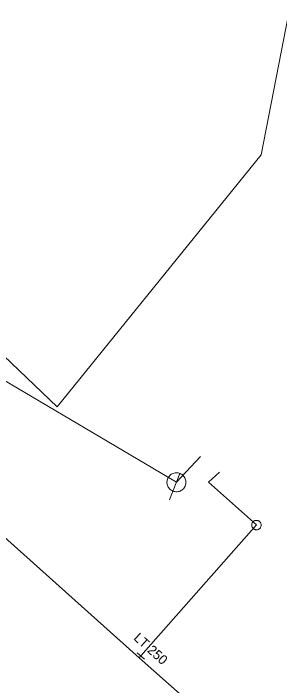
# Model space of a CAD drawing. Extents: x -807203 to -805207, y -993656 to -992505.
# Drawn here: x -805939.1 to -805911, y -993352 to -993281.2 of the extents above; entities that cross this region are included whole.
import ezdxf

# ---------------------------------------------------------------- set-up
doc = ezdxf.new("R2010")
doc.units = 0
doc.header["$LTSCALE"] = 0.4
for name, color, linetype, lineweight in [('1', 7, 'Continuous', 13), ('11', 7, 'Continuous', 13), ('13', 7, 'Continuous', 13), ('14', 7, 'Continuous', 25), ('17', 7, 'Continuous', 25), ('22', 7, 'Continuous', 13), ('23', 7, 'Continuous', 13), ('34', 7, 'Continuous', 13)]:
    doc.layers.add(name, color=color, linetype=linetype, lineweight=lineweight)

msp = doc.modelspace()

# ---------------------------------------------------------------- linework, layer by layer
at = {"layer": '11'}
msp.add_lwpolyline([(-805919.353, -993327.844), (-805921.873, -993330.572), (-805943.489, -993317.82)], dxfattribs=at)
at = {"layer": '13'}
msp.add_line((-805925.634, -993348.875), (-805913.442, -993335.051), dxfattribs=at)
for points in [[(-805946.515, -993311.099), (-805934.429, -993322.629), (-805912.935, -993296.079), (-805909.259, -993277.126), (-805870.365, -993236.01)], [(-805913.442, -993335.051), (-805918.497, -993330.563), (-805917.348, -993329.5)]]:
    msp.add_lwpolyline(points, dxfattribs=at)
at = {"layer": '14', "lineweight": 13}
msp.add_line((-805925.796, -993349.072), (-805925.634, -993348.875), dxfattribs=at)
at = {"layer": '17'}
msp.add_lwpolyline([(-805980.27, -993297.811), (-805964.539, -993313.096), (-805944.059, -993332.754), (-805925.796, -993349.072), (-805905.688, -993366.883), (-805894.556, -993375.978), (-805881.298, -993386.71), (-805877.651, -993389.561), (-805871.269, -993394.798), (-805850.666, -993411.467), (-805839.3, -993421.037), (-805830.275, -993428.564)], dxfattribs=at)
at = {"layer": '22'}
msp.add_line((-805922.615, -993332.429), (-805921.501, -993329.643), dxfattribs=at)
msp.add_lwpolyline([(-805920.944, -993330.943), (-805920.909, -993330.84), (-805920.886, -993330.733), (-805920.874, -993330.623), (-805920.874, -993330.515), (-805920.886, -993330.405), (-805920.91, -993330.299), (-805920.947, -993330.195), (-805920.993, -993330.096), (-805921.051, -993330.002), (-805921.117, -993329.916), (-805921.194, -993329.838), (-805921.279, -993329.768), (-805921.37, -993329.708), (-805921.467, -993329.658), (-805921.57, -993329.619), (-805921.676, -993329.592), (-805921.784, -993329.576), (-805921.894, -993329.572), (-805922.003, -993329.581), (-805922.11, -993329.6), (-805922.215, -993329.633), (-805922.316, -993329.676), (-805922.412, -993329.73), (-805922.5, -993329.793), (-805922.581, -993329.866), (-805922.654, -993329.948), (-805922.718, -993330.038), (-805922.771, -993330.133), (-805922.814, -993330.235), (-805922.845, -993330.339), (-805922.865, -993330.447), (-805922.872, -993330.556), (-805922.868, -993330.665), (-805922.853, -993330.774), (-805922.824, -993330.88), (-805922.785, -993330.982), (-805922.735, -993331.079), (-805922.674, -993331.17), (-805922.604, -993331.254), (-805922.525, -993331.33), (-805922.438, -993331.397), (-805922.345, -993331.454), (-805922.245, -993331.5), (-805922.141, -993331.535), (-805922.034, -993331.558), (-805921.926, -993331.57), (-805921.816, -993331.57), (-805921.707, -993331.558), (-805921.6, -993331.534), (-805921.497, -993331.499), (-805921.398, -993331.452), (-805921.304, -993331.395), (-805921.218, -993331.328), (-805921.14, -993331.252), (-805921.069, -993331.168), (-805921.009, -993331.076), (-805920.959, -993330.978)], close=True, dxfattribs=at)
at = {"layer": '23'}
for points in [[(-805913.113, -993334.704), (-805913.155, -993334.672), (-805913.2, -993334.644), (-805913.246, -993334.623), (-805913.296, -993334.605), (-805913.346, -993334.592), (-805913.399, -993334.586), (-805913.451, -993334.584), (-805913.502, -993334.588), (-805913.554, -993334.597), (-805913.604, -993334.611), (-805913.653, -993334.631), (-805913.7, -993334.656), (-805913.743, -993334.685), (-805913.782, -993334.719), (-805913.818, -993334.756), (-805913.851, -993334.799), (-805913.878, -993334.842), (-805913.901, -993334.891), (-805913.919, -993334.938), (-805913.932, -993334.989), (-805913.938, -993335.042), (-805913.939, -993335.094), (-805913.935, -993335.147), (-805913.927, -993335.198), (-805913.912, -993335.248), (-805913.891, -993335.297), (-805913.867, -993335.342), (-805913.837, -993335.385), (-805913.803, -993335.425), (-805913.766, -993335.462), (-805913.725, -993335.494), (-805913.68, -993335.521), (-805913.633, -993335.545), (-805913.584, -993335.562), (-805913.534, -993335.573), (-805913.482, -993335.58), (-805913.429, -993335.583), (-805913.376, -993335.579), (-805913.325, -993335.569)], [(-805913.325, -993335.569), (-805913.276, -993335.556), (-805913.227, -993335.535), (-805913.181, -993335.511), (-805913.137, -993335.48), (-805913.098, -993335.447), (-805913.062, -993335.41), (-805913.03, -993335.368), (-805913.002, -993335.324), (-805912.979, -993335.276), (-805912.962, -993335.227), (-805912.949, -993335.176), (-805912.941, -993335.125), (-805912.941, -993335.072), (-805912.944, -993335.02), (-805912.953, -993334.969), (-805912.968, -993334.918), (-805912.988, -993334.869), (-805913.013, -993334.823), (-805913.043, -993334.781), (-805913.076, -993334.741), (-805913.113, -993334.704), (-805913.155, -993334.672), (-805913.2, -993334.644), (-805913.246, -993334.623), (-805913.296, -993334.605), (-805913.346, -993334.592), (-805913.399, -993334.586), (-805913.451, -993334.584), (-805913.502, -993334.588), (-805913.554, -993334.597), (-805913.604, -993334.611), (-805913.653, -993334.631), (-805913.7, -993334.656), (-805913.743, -993334.685), (-805913.782, -993334.719), (-805913.818, -993334.756), (-805913.851, -993334.799), (-805913.878, -993334.842), (-805913.901, -993334.891)], [(-805913.013, -993334.823), (-805913.043, -993334.781), (-805913.076, -993334.741), (-805913.113, -993334.704)], [(-805913.901, -993334.891), (-805913.919, -993334.938), (-805913.932, -993334.989), (-805913.938, -993335.042), (-805913.939, -993335.094), (-805913.935, -993335.147), (-805913.927, -993335.198), (-805913.912, -993335.248), (-805913.891, -993335.297), (-805913.867, -993335.342), (-805913.837, -993335.385), (-805913.803, -993335.425), (-805913.766, -993335.462), (-805913.725, -993335.494), (-805913.68, -993335.521), (-805913.633, -993335.545), (-805913.584, -993335.562), (-805913.534, -993335.573), (-805913.482, -993335.58), (-805913.429, -993335.583), (-805913.376, -993335.579), (-805913.325, -993335.569), (-805913.276, -993335.556), (-805913.227, -993335.535), (-805913.181, -993335.511), (-805913.137, -993335.48), (-805913.098, -993335.447), (-805913.062, -993335.41), (-805913.03, -993335.368), (-805913.002, -993335.324), (-805912.979, -993335.276), (-805912.962, -993335.227), (-805912.949, -993335.176), (-805912.941, -993335.125), (-805912.941, -993335.072), (-805912.944, -993335.02), (-805912.953, -993334.969), (-805912.968, -993334.918), (-805912.988, -993334.869), (-805913.013, -993334.823)]]:
    msp.add_lwpolyline(points, dxfattribs=at)
at = {"layer": '34'}
msp.add_line((-805926.021, -993348.558), (-805925.247, -993349.192), dxfattribs=at)

# ---------------------------------------------------------------- texts
at = {"layer": '1'}
msp.add_text('LT 250', height=1, rotation=318, dxfattribs=at).set_placement((-805926.459, -993347.087))

doc.saveas('drawing.dxf')
